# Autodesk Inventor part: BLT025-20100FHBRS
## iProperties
Shininess: 28.0
Length Units: 11272
Angle Units: 11279
Time Units: 11290
Mass Units: 11286
Length Display Precision: 4
Angle Display Precision: 2
Compacted: True
Created: 2004-02
Part Number: BLT025-20100FHBRS
Cost Center: 0 lbmass
Material: Brass, C360
Description: FHMS 025-20x1 BRS
Document SubType Name: Modeling
Designer: KArthur
Authority: 0.06 in^3
Density: 7.84
Volumn: 0.0334175022831377
Area: 0.7931629180511741
PropertySet Name: Model Information
Control State: 0
Master: False
Checked Out: False
TotalMass: 0 lbmass
TotalVolume: 0.06 in^3
Author: KArthur
Title: Flat Head Brass Screw
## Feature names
1. Revolution1
2. Extrusion1
3. Chamfer1
